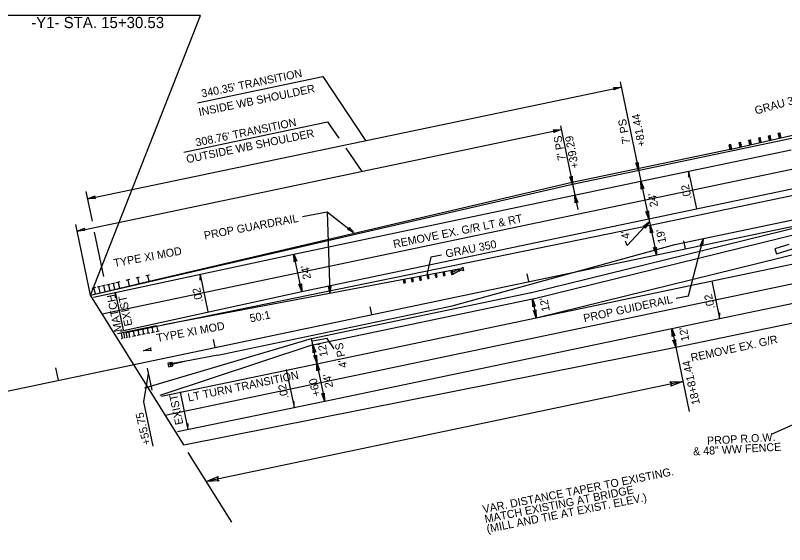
# Model space of a CAD drawing. Extents: x 2389694 to 2405615, y 547005 to 573532.
# Drawn here: x 2390180.4 to 2390660.7, y 552379.6 to 552710.1 of the extents above; entities that cross this region are included whole.
import ezdxf

# ---------------------------------------------------------------- set-up
doc = ezdxf.new("R2010")
doc.units = 0
for name, color, linetype in [('Old_Level_11', 7, 'Continuous'), ('Old_Level_22', 7, 'Continuous'), ('Prop Cable Guiderail Anchor Unit CELL', 7, 'Continuous'), ('Prop Cable Guiderail Double Face', 7, 'Continuous'), ('Prop Dimension', 7, 'Continuous'), ('Prop Dimension Text', 7, 'Continuous'), ('Prop DSN Text', 7, 'Continuous'), ('Prop EOT', 7, 'Continuous'), ('Prop GRAU 350 Approach CELL', 7, 'Continuous'), ('Prop Guardrail', 7, 'Continuous'), ('Prop Guardrail Anchor Unit CELL', 7, 'Continuous'), ('Prop Horizontal Alignment', 7, 'Continuous'), ('Prop Horizontal Alignment Tick Large', 7, 'Continuous'), ('Prop Horizontal Alignment Tick Small', 7, 'Continuous'), ('Prop Lane Arrow Left Turn CELL', 7, 'Continuous'), ('Prop Lane Lines', 7, 'Continuous'), ('Prop Structure Anchor Unit CELL', 7, 'Continuous'), ('Prop Super Arrow 1 Lane CELL', 7, 'Continuous'), ('Prop Superelevation Label', 7, 'Continuous')]:
    doc.layers.add(name, color=color, linetype=linetype)

# ---------------------------------------------------------------- blocks, each defined once
blk = doc.blocks.new('TERM')
at = {"layer": 'Old_Level_11'}
blk.add_lwpolyline([(-0.01375, 0.00225), (0, 0), (-0.01375, -0.0025), (-0.012, 0)], close=True, dxfattribs=at)
blk = doc.blocks.new('350 GRAU TR')
at = {"layer": 'Prop Guardrail Anchor Unit CELL'}
for p, q in [((0.45, -0.01), (47.19, -0.94)), ((2.99, -0.06), (2.93, -3.06)), ((3.96, -1.58), (2.93, -3.06)), ((2.93, -3.06), (3.93, -3.08)), ((2.96, -1.56), (3.99, -0.08)), ((2.96, -1.56), (3.96, -1.58)), ((3.93, -3.08), (2.96, -1.56)), ((2.99, -0.06), (3.99, -0.08)), ((3.96, -1.58), (2.99, -0.06)), ((3.99, -0.08), (3.93, -3.08)), ((3.99, -0.08), (3.96, -1.58)), ((9.29, -0.19), (9.23, -3.24)), ((10.26, -1.73), (9.23, -3.24)), ((9.23, -3.24), (10.23, -3.26)), ((9.26, -1.71), (10.29, -0.21)), ((9.26, -1.71), (10.26, -1.73)), ((10.23, -3.26), (9.26, -1.71)), ((9.29, -0.19), (10.26, -1.73)), ((10.29, -0.21), (10.23, -3.26)), ((15.59, -0.31), (15.53, -3.36)), ((16.56, -1.86), (15.53, -3.36)), ((15.53, -3.36), (16.53, -3.38)), ((15.56, -1.84), (16.59, -0.33)), ((15.56, -1.84), (16.56, -1.86)), ((16.53, -3.38), (15.56, -1.84)), ((15.59, -0.31), (16.56, -1.86)), ((16.59, -0.33), (16.53, -3.38)), ((21.89, -0.44), (21.83, -3.47)), ((22.86, -1.98), (21.83, -3.47)), ((21.83, -3.47), (22.83, -3.49)), ((21.86, -1.96), (22.89, -0.46)), ((21.86, -1.96), (22.86, -1.98)), ((22.83, -3.49), (21.86, -1.96)), ((21.89, -0.44), (22.89, -0.46)), ((21.89, -0.44), (22.86, -1.98)), ((22.89, -0.46), (22.83, -3.49)), ((28.19, -0.56), (28.13, -3.7)), ((29.16, -2.15), (28.13, -3.7)), ((28.13, -3.7), (29.13, -3.72)), ((28.16, -2.13), (29.19, -0.58)), ((28.16, -2.13), (29.16, -2.15)), ((29.13, -3.72), (28.16, -2.13)), ((28.19, -0.56), (29.16, -2.15)), ((29.19, -0.58), (29.13, -3.72)), ((34.49, -0.69), (34.43, -3.69)), ((35.46, -2.21), (34.43, -3.69)), ((34.43, -3.69), (35.43, -3.71)), ((34.46, -2.19), (35.49, -0.71)), ((34.46, -2.19), (35.46, -2.21)), ((35.43, -3.71), (34.46, -2.19)), ((34.49, -0.69), (35.46, -2.21)), ((35.49, -0.71), (35.43, -3.71)), ((40.79, -0.82), (40.73, -3.88)), ((41.76, -2.37), (40.73, -3.88)), ((40.73, -3.88), (41.73, -3.9)), ((40.76, -2.35), (41.79, -0.84)), ((40.76, -2.35), (41.76, -2.37)), ((41.73, -3.9), (40.76, -2.35)), ((40.79, -0.82), (41.76, -2.37)), ((41.79, -0.84), (41.73, -3.9)), ((41.73, -3.9), (46.66, -2.43)), ((41.76, -2.37), (46.69, -0.93)), ((46.69, -0.93), (46.66, -2.43)), ((47.69, -0.95), (46.66, -2.43)), ((46.66, -2.43), (47.16, -2.44)), ((46.66, -2.43), (47.66, -2.45)), ((47.66, -2.45), (46.69, -0.93)), ((47.22, -1.63), (47.22, -1.02)), ((47.22, -1.02), (49.27, -1.02)), ((47.22, -2.24), (47.22, -1.63)), ((49.26, -2.25), (47.22, -2.24)), ((47.69, -0.95), (47.66, -2.45)), ((50.44, -3.11), (49.26, -2.25)), ((49.27, -1.02), (50.45, -0.17)), ((50.45, -0.17), (50.44, -3.11))]:
    blk.add_line(p, q, dxfattribs=at)

msp = doc.modelspace()

# ---------------------------------------------------------------- linework, layer by layer
at = {"layer": 'Prop Cable Guiderail Anchor Unit CELL'}
for p, q in [((2390287.09, 552494.07), (2390277.26, 552492.38)), ((2390287.09, 552494.07), (2390277.28, 552492.12)), ((2390287.09, 552494.07), (2390277.32, 552491.89)), ((2390306.71, 552497.96), (2390287.09, 552494.07)), ((2390287.09, 552494.07), (2390287.09, 552494.07)), ((2390275.81, 552493.11), (2390278.26, 552493.59)), ((2390276.3, 552490.66), (2390275.81, 552493.11)), ((2390276.3, 552490.66), (2390278.75, 552491.14)), ((2390276.87, 552492.57), (2390277.49, 552492.7)), ((2390277.07, 552491.55), (2390276.87, 552492.57)), ((2390277.07, 552491.55), (2390277.69, 552491.67)), ((2390277.69, 552491.67), (2390277.49, 552492.7)), ((2390278.75, 552491.14), (2390278.26, 552493.59))]:
    msp.add_line(p, q, dxfattribs=at)
at = {"layer": 'Prop Cable Guiderail Double Face'}
for p, q in [((2390592.08, 552567.02), (2390668.8, 552583.11)), ((2390453, 552528.65), (2390592.08, 552567.02)), ((2390306.71, 552497.96), (2390453, 552528.65))]:
    msp.add_line(p, q, dxfattribs=at)
at = {"layer": 'Prop Dimension'}
for p, q in [((2390294.05, 552655.46), (2390372.28, 552671.89)), ((2390372.28, 552671.89), (2390399.03, 552631.87)), ((2390557.96, 552668.52), (2390570.96, 552606.53)), ((2390225.52, 552595.47), (2390558.62, 552665.35)), ((2390285.52, 552624.66), (2390375.34, 552643.54)), ((2390375.34, 552643.54), (2390382.34, 552633.45)), ((2390218.95, 552575.38), (2390521.13, 552638.78)), ((2390520.65, 552641.08), (2390529.71, 552597.87)), ((2390386.69, 552627.18), (2390396.74, 552612.68)), ((2390528.28, 552604.72), (2390531.65, 552588.8)), ((2390570.96, 552606.53), (2390575.89, 552583.04)), ((2390228.46, 552581.47), (2390224.57, 552600.02)), ((2390562.36, 552566.33), (2390576.19, 552581.14)), ((2390575.89, 552583.04), (2390576.71, 552579.12)), ((2390227.33, 552535.41), (2390218.07, 552579.58)), ((2390576.71, 552579.12), (2390580.61, 552560.53)), ((2390235.69, 552546.98), (2390229.87, 552574.74)), ((2390562.36, 552566.33), (2390561.38, 552569.13)), ((2390359.17, 552537.57), (2390354.24, 552561.06)), ((2390503.17, 552533.04), (2390505.63, 552521.3)), ((2389717.95, 552379.55), (2390379.47, 552518.33)), ((2390590.26, 552514.53), (2390592.73, 552502.78)), ((2390368.61, 552492.55), (2390365.33, 552508.21)), ((2390375.08, 552508.26), (2390366, 552506.58)), ((2390379.46, 552501.87), (2390375.08, 552508.26)), ((2390592.73, 552502.78), (2390601.15, 552462.66)), ((2390262.67, 552489.82), (2390265.57, 552475.99)), ((2390368.61, 552492.55), (2390373.54, 552469.06)), ((2390263.39, 552486.36), (2390260.4, 552468.83)), ((2390597.19, 552481.53), (2390299.45, 552419.07)), ((2390260.4, 552468.83), (2390266.21, 552441.11)), ((2390288.17, 552437.19), (2390315.36, 552393.5))]:
    msp.add_line(p, q, dxfattribs=at)
for points in [[(2390553.74, 552665.13), (2390558.62, 552665.35), (2390554.07, 552663.56), (2390554.49, 552664.47)], [(2390516.25, 552638.56), (2390521.13, 552638.78), (2390516.58, 552636.99), (2390517, 552637.9)], [(2390569.32, 552618.26), (2390569.53, 552613.38), (2390567.75, 552617.93), (2390568.66, 552617.51)], [(2390528.07, 552609.61), (2390528.28, 552604.72), (2390526.5, 552609.28), (2390527.41, 552608.86)], [(2390571.17, 552601.64), (2390570.96, 552606.53), (2390572.74, 552601.97), (2390571.83, 552602.39)], [(2390230.4, 552595.72), (2390225.52, 552595.47), (2390230.06, 552597.29), (2390229.64, 552596.38)], [(2390529.92, 552592.99), (2390529.71, 552597.87), (2390531.49, 552593.32), (2390530.58, 552593.74)], [(2390575.69, 552587.92), (2390575.89, 552583.04), (2390574.12, 552587.59), (2390575.02, 552587.17)], [(2390572.55, 552578.38), (2390576.19, 552581.14), (2390573.68, 552577.29), (2390573.49, 552578.25)], [(2390223.83, 552575.64), (2390218.95, 552575.38), (2390223.49, 552577.21), (2390223.07, 552576.29)], [(2390576.92, 552574.24), (2390576.71, 552579.12), (2390578.49, 552574.57), (2390577.58, 552574.99)], [(2390354.45, 552556.18), (2390354.24, 552561.06), (2390356.02, 552556.51), (2390355.11, 552556.93)], [(2390580.41, 552565.41), (2390580.61, 552560.53), (2390578.84, 552565.08), (2390579.75, 552564.66)], [(2390358.96, 552542.46), (2390359.17, 552537.57), (2390357.39, 552542.13), (2390358.3, 552541.7)], [(2390503.37, 552528.16), (2390503.17, 552533.04), (2390504.94, 552528.48), (2390504.03, 552528.91)], [(2390505.43, 552526.18), (2390505.63, 552521.3), (2390503.86, 552525.85), (2390504.76, 552525.43)], [(2390590.47, 552509.64), (2390590.26, 552514.53), (2390592.04, 552509.97), (2390591.13, 552510.4)], [(2390366.35, 552499.41), (2390366.15, 552504.3), (2390367.93, 552499.74), (2390367.02, 552500.16)], [(2390592.52, 552507.67), (2390592.73, 552502.78), (2390590.95, 552507.34), (2390591.86, 552506.92)], [(2390265.3, 552500.79), (2390260.42, 552500.53), (2390264.96, 552502.36), (2390264.54, 552501.44)], [(2390368.3, 552497.94), (2390368.51, 552493.06), (2390366.73, 552497.62), (2390367.64, 552497.19)], [(2390368.71, 552488.18), (2390368.51, 552493.06), (2390370.28, 552488.51), (2390369.37, 552488.93)], [(2390589.05, 552481.19), (2390597.19, 552481.53), (2390589.59, 552478.57), (2390590.3, 552480.08)], [(2390373.28, 552474.22), (2390373.48, 552469.34), (2390371.71, 552473.89), (2390372.62, 552473.47)], [(2390307.59, 552419.41), (2390299.45, 552419.07), (2390307.04, 552422.03), (2390306.33, 552420.51)]]:
    msp.add_lwpolyline(points, close=True, dxfattribs=at)
at = {"layer": 'Prop Dimension Text'}
for p, q in [((2390295.92, 552710.1), (2390175.58, 552710.1)), ((2390227.33, 552535.41), (2390295.92, 552710.1))]:
    msp.add_line(p, q, dxfattribs=at)
at = {"layer": 'Prop DSN Text'}
for p, q in [((2390359.59, 552584.52), (2390375.09, 552587.42)), ((2390375.09, 552587.42), (2390391.57, 552574.5)), ((2390375.09, 552587.42), (2390376.77, 552536.86)), ((2390600.66, 552534.91), (2390609.76, 552570.37)), ((2390439.69, 552559.07), (2390437.33, 552547.96)), ((2390446.42, 552560.41), (2390439.69, 552559.07)), ((2390593.03, 552533.45), (2390600.66, 552534.91)), ((2390652.56, 552448.6), (2390691.44, 552465.86))]:
    msp.add_line(p, q, dxfattribs=at)
at = {"layer": 'Prop EOT'}
for p, q in [((2390528.28, 552604.72), (2390692.03, 552639.08)), ((2390570.96, 552606.53), (2390664.65, 552626.18)), ((2390575.89, 552583.04), (2390725.14, 552614.35)), ((2390576.71, 552579.12), (2390725.97, 552610.43)), ((2390227.33, 552535.41), (2390528.28, 552604.72)), ((2390354.24, 552561.06), (2390570.96, 552606.53)), ((2390501.81, 552536.83), (2390729.13, 552592.69)), ((2390502.77, 552532.95), (2390730.08, 552588.81)), ((2390359.17, 552537.57), (2390575.89, 552583.04)), ((2390249.33, 552512.12), (2390576.71, 552579.12)), ((2390229.14, 552534.09), (2390354.24, 552561.06)), ((2390590.26, 552514.53), (2390739.52, 552545.84)), ((2390246.01, 552512.97), (2390359.17, 552537.57)), ((2390365.33, 552508.21), (2390502.35, 552536.96)), ((2390285.51, 552441.93), (2390227.33, 552535.41)), ((2390366.15, 552504.3), (2390503.17, 552533.04)), ((2390592.73, 552502.78), (2390741.98, 552534.09)), ((2390373.54, 552469.06), (2390590.26, 552514.53)), ((2390261.23, 552477.52), (2390365.33, 552508.21)), ((2390366.15, 552504.3), (2390270.59, 552472.76)), ((2390285.51, 552441.93), (2390592.73, 552502.78)), ((2390281.72, 552450.21), (2390373.54, 552469.06))]:
    msp.add_line(p, q, dxfattribs=at)
at = {"layer": 'Prop GRAU 350 Approach CELL'}
for p, q in [((2390627.2, 552626.5), (2390675.97, 552637.61)), ((2390644.47, 552633.56), (2390645.45, 552633.78)), ((2390645.15, 552630.59), (2390644.47, 552633.56)), ((2390645.79, 552632.29), (2390644.47, 552633.56)), ((2390645.45, 552633.78), (2390644.81, 552632.07)), ((2390646.12, 552630.81), (2390645.45, 552633.78)), ((2390650.62, 552634.95), (2390651.59, 552635.17)), ((2390651.29, 552631.99), (2390650.62, 552634.95)), ((2390651.93, 552633.69), (2390650.62, 552634.95)), ((2390651.59, 552635.17), (2390650.96, 552633.47)), ((2390650.96, 552633.47), (2390651.93, 552633.69)), ((2390650.96, 552633.47), (2390652.27, 552632.21)), ((2390651.29, 552631.99), (2390651.93, 552633.69)), ((2390652.27, 552632.21), (2390651.59, 552635.17)), ((2390656.74, 552636.44), (2390657.72, 552636.67)), ((2390657.44, 552633.39), (2390656.74, 552636.44)), ((2390658.06, 552635.14), (2390656.74, 552636.44)), ((2390657.72, 552636.67), (2390657.09, 552634.91)), ((2390657.09, 552634.91), (2390658.06, 552635.14)), ((2390657.09, 552634.91), (2390658.41, 552633.61)), ((2390657.44, 552633.39), (2390658.06, 552635.14)), ((2390658.41, 552633.61), (2390657.72, 552636.67)), ((2390627.09, 552629.54), (2390626.11, 552629.34)), ((2390626.72, 552626.4), (2390626.11, 552629.34)), ((2390626.11, 552629.34), (2390627.39, 552628.07)), ((2390626.41, 552627.87), (2390627.09, 552629.54)), ((2390627.69, 552626.6), (2390627.09, 552629.54)), ((2390632.19, 552630.71), (2390633.17, 552630.93)), ((2390632.86, 552627.79), (2390632.19, 552630.71)), ((2390633.5, 552629.47), (2390632.19, 552630.71)), ((2390633.17, 552630.93), (2390632.53, 552629.25)), ((2390632.53, 552629.25), (2390633.5, 552629.47)), ((2390632.53, 552629.25), (2390633.84, 552628.01)), ((2390633.5, 552629.47), (2390632.86, 552627.79)), ((2390633.84, 552628.01), (2390633.17, 552630.93)), ((2390633.84, 552628.01), (2390633.5, 552629.47)), ((2390638.33, 552632.16), (2390639.3, 552632.39)), ((2390639, 552629.19), (2390638.33, 552632.16)), ((2390639.64, 552630.9), (2390638.33, 552632.16)), ((2390639.3, 552632.39), (2390638.67, 552630.68)), ((2390638.67, 552630.68), (2390639.64, 552630.9)), ((2390638.67, 552630.68), (2390639.98, 552629.41)), ((2390639, 552629.19), (2390639.64, 552630.9)), ((2390639.98, 552629.41), (2390639.3, 552632.39)), ((2390644.81, 552632.07), (2390645.79, 552632.29)), ((2390644.81, 552632.07), (2390646.12, 552630.81)), ((2390645.15, 552630.59), (2390645.79, 552632.29)), ((2390651.29, 552631.99), (2390652.27, 552632.21)), ((2390626.41, 552627.87), (2390627.39, 552628.07)), ((2390627.69, 552626.6), (2390626.41, 552627.87)), ((2390627.39, 552628.07), (2390626.72, 552626.4)), ((2390626.72, 552626.4), (2390627.69, 552626.6)), ((2390632.86, 552627.79), (2390633.84, 552628.01))]:
    msp.add_line(p, q, dxfattribs=at)
at = {"layer": 'Prop Guardrail'}
for p, q in [((2390626.72, 552626.4), (2390528.07, 552605.7)), ((2390528.05, 552605.7), (2390263.85, 552543.95)), ((2390273.12, 552516.96), (2390420.54, 552544.83))]:
    msp.add_line(p, q, dxfattribs=at)
at = {"layer": 'Prop Horizontal Alignment'}
msp.add_line((2389717.95, 552379.55), (2390729.87, 552591.84), dxfattribs=at)
at = {"layer": 'Prop Horizontal Alignment Tick Large'}
msp.add_line((2390207.3, 552482.21), (2390205.66, 552490.04), dxfattribs=at)
at = {"layer": 'Prop Horizontal Alignment Tick Small'}
for p, q in [((2390598.78, 552564.34), (2390597.75, 552569.23)), ((2390500.91, 552543.81), (2390499.88, 552548.7)), ((2390403.04, 552523.27), (2390402.01, 552528.17)), ((2390305.17, 552502.74), (2390304.14, 552507.64))]:
    msp.add_line(p, q, dxfattribs=at)
at = {"layer": 'Prop Lane Arrow Left Turn CELL'}
for p, q in [((2390663.33, 552567), (2390654.56, 552564.39)), ((2390654.56, 552564.39), (2390655.5, 552561.23)), ((2390655.5, 552561.23), (2390665.61, 552564.24))]:
    msp.add_line(p, q, dxfattribs=at)
at = {"layer": 'Prop Lane Lines'}
for p, q in [((2390234.62, 552523.7), (2390722.68, 552626.09)), ((2390505.63, 552521.3), (2390732.94, 552577.16)), ((2390505.63, 552521.3), (2390734.59, 552569.33)), ((2390371.08, 552480.81), (2390737.05, 552557.58)), ((2390368.61, 552492.55), (2390505.63, 552521.3)), ((2390271.53, 552472.19), (2390368.61, 552492.55)), ((2390274, 552460.44), (2390371.08, 552480.81))]:
    msp.add_line(p, q, dxfattribs=at)
at = {"layer": 'Prop Structure Anchor Unit CELL'}
for p, q in [((2390255.72, 552546.2), (2390257.95, 552546.72)), ((2390257.75, 552542.57), (2390256.84, 552546.46)), ((2390261.81, 552547.63), (2390264.04, 552548.15)), ((2390263.84, 552544), (2390262.92, 552547.89)), ((2390227.33, 552535.41), (2390263.84, 552544)), ((2390234.43, 552541.19), (2390236.66, 552541.71)), ((2390237.47, 552541.91), (2390239.7, 552542.43)), ((2390239.5, 552538.27), (2390238.59, 552542.17)), ((2390240.51, 552542.62), (2390242.74, 552543.15)), ((2390242.54, 552538.99), (2390241.63, 552542.88)), ((2390243.56, 552543.34), (2390245.79, 552543.86)), ((2390245.59, 552539.7), (2390244.67, 552543.6)), ((2390249.64, 552544.77), (2390251.87, 552545.29)), ((2390251.67, 552541.14), (2390250.75, 552545.03)), ((2390228.35, 552539.76), (2390230.58, 552540.28)), ((2390230.38, 552536.13), (2390229.46, 552540.02)), ((2390231.39, 552540.48), (2390233.62, 552541)), ((2390233.42, 552536.84), (2390232.5, 552540.74)), ((2390236.46, 552537.56), (2390235.54, 552541.45)), ((2390268.6, 552516.12), (2390244.1, 552511.2)), ((2390253.9, 552513.17), (2390254.55, 552509.95)), ((2390256.84, 552513.76), (2390257.49, 552510.54)), ((2390259.78, 552514.35), (2390260.43, 552511.13)), ((2390262.72, 552514.94), (2390263.37, 552511.72)), ((2390265.66, 552515.53), (2390266.31, 552512.31)), ((2390268.27, 552512.71), (2390270.23, 552513.1)), ((2390268.6, 552516.12), (2390269.25, 552512.9)), ((2390246.36, 552511.65), (2390247.01, 552508.43)), ((2390246.64, 552508.36), (2390247.38, 552508.51)), ((2390247.89, 552511.96), (2390248.54, 552508.74)), ((2390248.17, 552508.67), (2390248.91, 552508.82)), ((2390249.43, 552512.27), (2390250.07, 552509.05)), ((2390249.7, 552508.97), (2390250.45, 552509.12)), ((2390250.96, 552512.58), (2390251.61, 552509.36)), ((2390251.23, 552509.28), (2390251.98, 552509.43)), ((2390253.57, 552509.75), (2390255.53, 552510.15)), ((2390256.51, 552510.34), (2390258.47, 552510.74)), ((2390259.45, 552510.93), (2390261.41, 552511.33)), ((2390262.39, 552511.52), (2390264.35, 552511.92)), ((2390265.33, 552512.12), (2390267.29, 552512.51))]:
    msp.add_line(p, q, dxfattribs=at)
at = {"layer": 'Prop Super Arrow 1 Lane CELL'}
for p, q in [((2390600.74, 552612.69), (2390605.65, 552589.28)), ((2390295.67, 552548.27), (2390300.59, 552524.86)), ((2390615.19, 552544.28), (2390620.11, 552520.79)), ((2390242.8, 552537.18), (2390247.71, 552513.77)), ((2390349.5, 552488.85), (2390354.43, 552465.36)), ((2390283.2, 552474.94), (2390288.13, 552451.45))]:
    msp.add_line(p, q, dxfattribs=at)
for points in [[(2390600.74, 552612.69), (2390600.67, 552609.1), (2390601.34, 552609.81)], [(2390295.67, 552548.27), (2390295.61, 552544.68), (2390296.28, 552545.39)], [(2390242.8, 552537.18), (2390242.74, 552533.59), (2390243.41, 552534.29)], [(2390620.11, 552520.79), (2390620.18, 552524.38), (2390619.51, 552523.68)], [(2390354.43, 552465.36), (2390354.49, 552468.95), (2390353.82, 552468.25)], [(2390288.13, 552451.45), (2390288.19, 552455.04), (2390287.52, 552454.34)]]:
    msp.add_lwpolyline(points, close=True, dxfattribs=at)

# ---------------------------------------------------------------- block references
at = {"layer": 'Prop DSN Text'}
for p, xscale, yscale, rotation in [((2390609.76, 552570.37), 300.00000000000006, 299.99999999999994, 75.61524656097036), ((2390376.77, 552536.86), 300, 300.00000000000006, -88.10508888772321)]:
    msp.add_blockref('TERM', p, dxfattribs=dict(at, xscale=xscale, yscale=yscale, rotation=rotation))
at = {"layer": 'Prop EOT', "xscale": 300, "yscale": 300.0000000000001, "rotation": -38.11269275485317}
msp.add_blockref('TERM', (2390391.57, 552574.5), dxfattribs=at)
at = {"layer": 'Prop Guardrail Anchor Unit CELL', "xscale": 0.8, "yscale": 0.7999999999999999, "rotation": 11.748089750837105}
msp.add_blockref('350 GRAU TR', (2390420.18, 552544.76), dxfattribs=at)

# ---------------------------------------------------------------- texts
at = {"layer": 'Old_Level_11'}
for s, p in [('+81.44', (2390573.89, 552628.63)), ("7' PS", (2390564.43, 552630.26)), ("7' PS", (2390524.16, 552619.84)), ('+39.29', (2390532.19, 552614.98))]:
    msp.add_text(s, height=5, rotation=100.6192, dxfattribs=at).set_placement(p)
at = {"layer": 'Old_Level_22'}
for s, rotation, p in [("340.35' TRANSITION ", 11.7115, (2390297.05, 552658.73)), ('INSIDE WB SHOULDER', 11.7115, (2390295.37, 552647.14)), ("308.76' TRANSITION ", 11.7115, (2390293.47, 552628.15)), ('OUTSIDE WB SHOULDER', 11.7115, (2390287.64, 552617.75)), ('VAR. DISTANCE TAPER TO EXISTING.', 11.3251, (2390472.66, 552399.12)), ('MATCH EXISTING AT BRIDGE', 11.3251, (2390473.89, 552392.99)), ('(MILL AND TIE AT EXIST. ELEV.)', 11.3251, (2390475.12, 552386.86))]:
    msp.add_text(s, height=5, rotation=rotation, dxfattribs=at).set_placement(p)
at = {"layer": 'Prop Dimension Text'}
msp.add_text('-Y1- STA. 15+30.53', height=7, dxfattribs=at).set_placement((2390190.26, 552702.15))
for s, rotation, p in [('GRAU 350', 15.4024, (2390642.74, 552648.14)), ("24'", 100.6192, (2390581.71, 552590.88)), ("19'", 100.6192, (2390586.75, 552568.34)), ("4'", 100.6192, (2390564.12, 552570.95)), ('GRAU 350', 11.0784, (2390449.44, 552558.75)), ('TYPE XI MOD', 10.5442, (2390242.26, 552552.88)), ("24'", 100.6192, (2390365.02, 552545.73)), ("12'", 100.6192, (2390514.09, 552525.65)), ('50:1', 11.0784, (2390327.24, 552518.37)), ('TYPE XI MOD', 10.5442, (2390269.04, 552506.08)), ("12'", 100.6192, (2390601.19, 552507.14)), ("12'", 100.6192, (2390375.54, 552497.43)), ("4' PS", 100.6192, (2390387.59, 552490.45)), ('18+81.44', 102.9063, (2390607.87, 552467.58)), ('LT TURN TRANSITION ', 11.7115, (2390288.55, 552468.89)), ("24'", 100.6192, (2390378.82, 552477.95)), ('+60', 102.9063, (2390370.88, 552472.78)), ('+55.75', 102.9063, (2390264.83, 552442.43))]:
    msp.add_text(s, height=5, rotation=rotation, dxfattribs=at).set_placement(p)
at = {"layer": 'Prop DSN Text'}
for s, rotation, p in [('PROP GUARDRAIL', 10.6708, (2390298.64, 552570.1)), ('REMOVE EX. G/R LT & RT', 11.4682, (2390416.81, 552564.71)), ('PROP GUIDERAIL', 12.3027, (2390535.62, 552518.43)), ('REMOVE EX. G/R', 12.3027, (2390602.63, 552493.78)), ('PROP R.O.W.', 3.1353, (2390612.38, 552441.95)), ('& 48" WW FENCE', 3.1353, (2390603.62, 552435.21))]:
    msp.add_text(s, height=5, rotation=rotation, dxfattribs=at).set_placement(p)
at = {"layer": 'Prop Super Arrow 1 Lane CELL'}
for s, p in [('MATCH', (2390247.09, 552512.96)), ('EXIST', (2390253.49, 552516.56))]:
    msp.add_text(s, height=5, rotation=101.848, dxfattribs=at).set_placement(p)
at = {"layer": 'Prop Superelevation Label'}
for s, p in [('.02', (2390602.64, 552595.78)), ('.02', (2390297.57, 552531.36)), ('.02', (2390617.1, 552527.3)), ('.02', (2390351.09, 552471.18)), ('EXIST', (2390285.27, 552454.94))]:
    msp.add_text(s, height=5, rotation=101.848, dxfattribs=at).set_placement(p)

doc.saveas('drawing.dxf')
